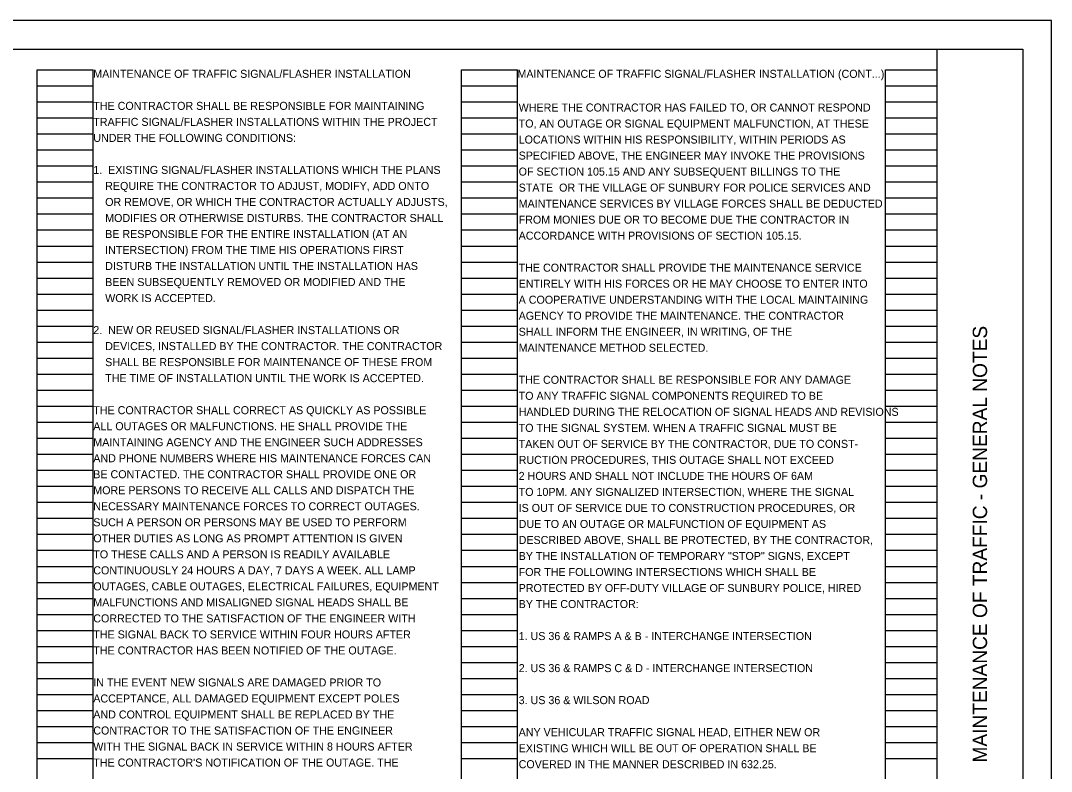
# Model space of a CAD drawing. Extents: x -6.8 to 34, y 0 to 22.
# Drawn here: x 15.97 to 34, y 8.88 to 22 of the extents above; entities that cross this region are included whole.
import ezdxf

# ---------------------------------------------------------------- set-up
doc = ezdxf.new("R2010")
doc.units = 0
for name, color, linetype in [('SH_Border', 7, 'Continuous'), ('SH_Cut_Line', 7, 'Continuous'), ('SH_Data', 7, 'Continuous'), ('SH_Text', 7, 'Continuous')]:
    doc.layers.add(name, color=color, linetype=linetype)

msp = doc.modelspace()

# ---------------------------------------------------------------- linework, layer by layer
at = {"layer": 'SH_Border'}
msp.add_line((32, 0.5), (32, 21.5), dxfattribs=at)
msp.add_lwpolyline([(1.5, 21.5), (33.5, 21.5), (33.5, 0.5), (1.5, 0.5)], close=True, dxfattribs=at)
at = {"layer": 'SH_Cut_Line'}
msp.add_lwpolyline([(0, 0), (34, 0), (34, 22), (0, 22)], close=True, dxfattribs=at)
at = {"layer": 'SH_Data'}
for p, q in [((16.26, 0.98), (16.26, 21.14)), ((16.26, 21.14), (17.24, 21.14)), ((17.24, 0.98), (17.24, 21.14)), ((23.68, 0.98), (23.68, 21.14)), ((23.68, 21.14), (24.66, 21.14)), ((24.66, 0.98), (24.66, 21.14)), ((31.1, 0.98), (31.1, 21.14)), ((31.1, 21.14), (32, 21.14)), ((32, 0.98), (32, 21.14)), ((16.26, 20.86), (17.24, 20.86)), ((23.68, 20.86), (24.66, 20.86)), ((31.1, 20.86), (32, 20.86)), ((16.26, 20.58), (17.24, 20.58)), ((23.68, 20.58), (24.66, 20.58)), ((31.1, 20.58), (32, 20.58)), ((16.26, 20.3), (17.24, 20.3)), ((23.68, 20.3), (24.66, 20.3)), ((31.1, 20.3), (32, 20.3)), ((16.26, 20.02), (17.24, 20.02)), ((23.68, 20.02), (24.66, 20.02)), ((31.1, 20.02), (32, 20.02)), ((16.26, 19.74), (17.24, 19.74)), ((23.68, 19.74), (24.66, 19.74)), ((31.1, 19.74), (32, 19.74)), ((16.26, 19.46), (17.24, 19.46)), ((23.68, 19.46), (24.66, 19.46)), ((31.1, 19.46), (32, 19.46)), ((16.26, 19.18), (17.24, 19.18)), ((23.68, 19.18), (24.66, 19.18)), ((31.1, 19.18), (32, 19.18)), ((16.26, 18.9), (17.24, 18.9)), ((23.68, 18.9), (24.66, 18.9)), ((31.1, 18.9), (32, 18.9)), ((16.26, 18.62), (17.24, 18.62)), ((23.68, 18.62), (24.66, 18.62)), ((31.1, 18.62), (32, 18.62)), ((16.26, 18.34), (17.24, 18.34)), ((23.68, 18.34), (24.66, 18.34)), ((31.1, 18.34), (32, 18.34)), ((16.26, 18.06), (17.24, 18.06)), ((23.68, 18.06), (24.66, 18.06)), ((31.1, 18.06), (32, 18.06)), ((16.26, 17.78), (17.24, 17.78)), ((23.68, 17.78), (24.66, 17.78)), ((31.1, 17.78), (32, 17.78)), ((16.26, 17.5), (17.24, 17.5)), ((23.68, 17.5), (24.66, 17.5)), ((31.1, 17.5), (32, 17.5)), ((16.26, 17.22), (17.24, 17.22)), ((23.68, 17.22), (24.66, 17.22)), ((31.1, 17.22), (32, 17.22)), ((16.26, 16.94), (17.24, 16.94)), ((23.68, 16.94), (24.66, 16.94)), ((31.1, 16.94), (32, 16.94)), ((16.26, 16.66), (17.24, 16.66)), ((23.68, 16.66), (24.66, 16.66)), ((31.1, 16.66), (32, 16.66)), ((16.26, 16.38), (17.24, 16.38)), ((23.68, 16.38), (24.66, 16.38)), ((31.1, 16.38), (32, 16.38)), ((16.26, 16.1), (17.24, 16.1)), ((23.68, 16.1), (24.66, 16.1)), ((31.1, 16.1), (32, 16.1)), ((16.26, 15.82), (17.24, 15.82)), ((23.68, 15.82), (24.66, 15.82)), ((31.1, 15.82), (32, 15.82)), ((16.26, 15.54), (17.24, 15.54)), ((23.68, 15.54), (24.66, 15.54)), ((31.1, 15.54), (32, 15.54)), ((16.26, 15.26), (17.24, 15.26)), ((23.68, 15.26), (24.66, 15.26)), ((31.1, 15.26), (32, 15.26)), ((16.26, 14.98), (17.24, 14.98)), ((23.68, 14.98), (24.66, 14.98)), ((31.1, 14.98), (32, 14.98)), ((16.26, 14.7), (17.24, 14.7)), ((23.68, 14.7), (24.66, 14.7)), ((31.1, 14.7), (32, 14.7)), ((16.26, 14.42), (17.24, 14.42)), ((23.68, 14.42), (24.66, 14.42)), ((31.1, 14.42), (32, 14.42)), ((16.26, 14.14), (17.24, 14.14)), ((23.68, 14.14), (24.66, 14.14)), ((31.1, 14.14), (32, 14.14)), ((16.26, 13.86), (17.24, 13.86)), ((23.68, 13.86), (24.66, 13.86)), ((31.1, 13.86), (32, 13.86)), ((16.26, 13.58), (17.24, 13.58)), ((23.68, 13.58), (24.66, 13.58)), ((31.1, 13.58), (32, 13.58)), ((16.26, 13.3), (17.24, 13.3)), ((23.68, 13.3), (24.66, 13.3)), ((31.1, 13.3), (32, 13.3)), ((16.26, 13.02), (17.24, 13.02)), ((23.68, 13.02), (24.66, 13.02)), ((31.1, 13.02), (32, 13.02)), ((16.26, 12.74), (17.24, 12.74)), ((23.68, 12.74), (24.66, 12.74)), ((31.1, 12.74), (32, 12.74)), ((16.26, 12.46), (17.24, 12.46)), ((23.68, 12.46), (24.66, 12.46)), ((31.1, 12.46), (32, 12.46)), ((16.26, 12.18), (17.24, 12.18)), ((23.68, 12.18), (24.66, 12.18)), ((31.1, 12.18), (32, 12.18)), ((16.26, 11.9), (17.24, 11.9)), ((23.68, 11.9), (24.66, 11.9)), ((31.1, 11.9), (32, 11.9)), ((16.26, 11.62), (17.24, 11.62)), ((23.68, 11.62), (24.66, 11.62)), ((31.1, 11.62), (32, 11.62)), ((16.26, 11.34), (17.24, 11.34)), ((23.68, 11.34), (24.66, 11.34)), ((31.1, 11.34), (32, 11.34)), ((16.26, 11.06), (17.24, 11.06)), ((23.68, 11.06), (24.66, 11.06)), ((31.1, 11.06), (32, 11.06)), ((16.26, 10.78), (17.24, 10.78)), ((23.68, 10.78), (24.66, 10.78)), ((31.1, 10.78), (32, 10.78)), ((16.26, 10.5), (17.24, 10.5)), ((23.68, 10.5), (24.66, 10.5)), ((31.1, 10.5), (32, 10.5)), ((16.26, 10.22), (17.24, 10.22)), ((23.68, 10.22), (24.66, 10.22)), ((31.1, 10.22), (32, 10.22)), ((16.26, 9.94), (17.24, 9.94)), ((23.68, 9.94), (24.66, 9.94)), ((31.1, 9.94), (32, 9.94)), ((16.26, 9.66), (17.24, 9.66)), ((23.68, 9.66), (24.66, 9.66)), ((31.1, 9.66), (32, 9.66)), ((16.26, 9.38), (17.24, 9.38)), ((23.68, 9.38), (24.66, 9.38)), ((31.1, 9.38), (32, 9.38)), ((16.26, 9.1), (17.24, 9.1)), ((23.68, 9.1), (24.66, 9.1)), ((31.1, 9.1), (32, 9.1))]:
    msp.add_line(p, q, dxfattribs=at)

# ---------------------------------------------------------------- texts
msp.add_text('MAINTENANCE OF TRAFFIC - GENERAL NOTES', height=0.25, rotation=90, dxfattribs=at).set_placement((32.875, 9.03))
at = {"layer": 'SH_Text'}
for s, p in [('MAINTENANCE OF TRAFFIC SIGNAL/FLASHER INSTALLATION', (17.24, 21)), ('MAINTENANCE OF TRAFFIC SIGNAL/FLASHER INSTALLATION (CONT...)', (24.66, 21)), ('THE CONTRACTOR SHALL BE RESPONSIBLE FOR MAINTAINING', (17.24, 20.44)), ('WHERE THE CONTRACTOR HAS FAILED TO, OR CANNOT RESPOND', (24.681, 20.411)), ('TRAFFIC SIGNAL/FLASHER INSTALLATIONS WITHIN THE PROJECT', (17.24, 20.16)), ('TO, AN OUTAGE OR SIGNAL EQUIPMENT MALFUNCTION, AT THESE', (24.681, 20.131)), ('UNDER THE FOLLOWING CONDITIONS:', (17.24, 19.88)), ('LOCATIONS WITHIN HIS RESPONSIBILITY, WITHIN PERIODS AS', (24.681, 19.851)), ('SPECIFIED ABOVE, THE ENGINEER MAY INVOKE THE PROVISIONS', (24.681, 19.571)), ('1.  EXISTING SIGNAL/FLASHER INSTALLATIONS WHICH THE PLANS', (17.24, 19.32)), ('OF SECTION 105.15 AND ANY SUBSEQUENT BILLINGS TO THE', (24.681, 19.291)), ('    REQUIRE THE CONTRACTOR TO ADJUST, MODIFY, ADD ONTO', (17.24, 19.04)), ('STATE  OR THE VILLAGE OF SUNBURY FOR POLICE SERVICES AND', (24.681, 19.011)), ('    OR REMOVE, OR WHICH THE CONTRACTOR ACTUALLY ADJUSTS,', (17.24, 18.76)), ('MAINTENANCE SERVICES BY VILLAGE FORCES SHALL BE DEDUCTED', (24.681, 18.731)), ('    MODIFIES OR OTHERWISE DISTURBS. THE CONTRACTOR SHALL', (17.24, 18.48)), ('FROM MONIES DUE OR TO BECOME DUE THE CONTRACTOR IN', (24.681, 18.451)), ('    BE RESPONSIBLE FOR THE ENTIRE INSTALLATION (AT AN', (17.24, 18.2)), ('ACCORDANCE WITH PROVISIONS OF SECTION 105.15.', (24.681, 18.171)), ('    INTERSECTION) FROM THE TIME HIS OPERATIONS FIRST', (17.24, 17.92)), ('    DISTURB THE INSTALLATION UNTIL THE INSTALLATION HAS', (17.24, 17.64)), ('THE CONTRACTOR SHALL PROVIDE THE MAINTENANCE SERVICE', (24.681, 17.611)), ('    BEEN SUBSEQUENTLY REMOVED OR MODIFIED AND THE', (17.24, 17.36)), ('ENTIRELY WITH HIS FORCES OR HE MAY CHOOSE TO ENTER INTO', (24.681, 17.331)), ('    WORK IS ACCEPTED.', (17.24, 17.08)), ('A COOPERATIVE UNDERSTANDING WITH THE LOCAL MAINTAINING', (24.681, 17.051)), ('AGENCY TO PROVIDE THE MAINTENANCE. THE CONTRACTOR', (24.681, 16.771)), ('2.  NEW OR REUSED SIGNAL/FLASHER INSTALLATIONS OR', (17.24, 16.52)), ('SHALL INFORM THE ENGINEER, IN WRITING, OF THE', (24.681, 16.491)), ('    DEVICES, INSTALLED BY THE CONTRACTOR. THE CONTRACTOR', (17.24, 16.24)), ('MAINTENANCE METHOD SELECTED.', (24.681, 16.211)), ('    SHALL BE RESPONSIBLE FOR MAINTENANCE OF THESE FROM', (17.24, 15.96)), ('    THE TIME OF INSTALLATION UNTIL THE WORK IS ACCEPTED.', (17.24, 15.68)), ('THE CONTRACTOR SHALL BE RESPONSIBLE FOR ANY DAMAGE', (24.681, 15.651)), ('TO ANY TRAFFIC SIGNAL COMPONENTS REQUIRED TO BE', (24.681, 15.371)), ('THE CONTRACTOR SHALL CORRECT AS QUICKLY AS POSSIBLE', (17.24, 15.12)), ('HANDLED DURING THE RELOCATION OF SIGNAL HEADS AND REVISIONS', (24.681, 15.091)), ('ALL OUTAGES OR MALFUNCTIONS. HE SHALL PROVIDE THE', (17.24, 14.84)), ('TO THE SIGNAL SYSTEM. WHEN A TRAFFIC SIGNAL MUST BE', (24.681, 14.811)), ('MAINTAINING AGENCY AND THE ENGINEER SUCH ADDRESSES', (17.24, 14.56)), ('TAKEN OUT OF SERVICE BY THE CONTRACTOR, DUE TO CONST-', (24.681, 14.531)), ('AND PHONE NUMBERS WHERE HIS MAINTENANCE FORCES CAN', (17.24, 14.28)), ('RUCTION PROCEDURES, THIS OUTAGE SHALL NOT EXCEED', (24.681, 14.251)), ('BE CONTACTED. THE CONTRACTOR SHALL PROVIDE ONE OR', (17.24, 14)), ('2 HOURS AND SHALL NOT INCLUDE THE HOURS OF 6AM', (24.681, 13.971)), ('MORE PERSONS TO RECEIVE ALL CALLS AND DISPATCH THE', (17.24, 13.72)), ('TO 10PM. ANY SIGNALIZED INTERSECTION, WHERE THE SIGNAL', (24.681, 13.691)), ('NECESSARY MAINTENANCE FORCES TO CORRECT OUTAGES.', (17.24, 13.44)), ('IS OUT OF SERVICE DUE TO CONSTRUCTION PROCEDURES, OR', (24.681, 13.411)), ('SUCH A PERSON OR PERSONS MAY BE USED TO PERFORM', (17.24, 13.16)), ('DUE TO AN OUTAGE OR MALFUNCTION OF EQUIPMENT AS', (24.681, 13.131)), ('OTHER DUTIES AS LONG AS PROMPT ATTENTION IS GIVEN', (17.24, 12.88)), ('DESCRIBED ABOVE, SHALL BE PROTECTED, BY THE CONTRACTOR,', (24.681, 12.851)), ('TO THESE CALLS AND A PERSON IS READILY AVAILABLE', (17.24, 12.6)), ('BY THE INSTALLATION OF TEMPORARY "STOP" SIGNS, EXCEPT', (24.681, 12.571)), ('CONTINUOUSLY 24 HOURS A DAY, 7 DAYS A WEEK. ALL LAMP', (17.24, 12.32)), ('FOR THE FOLLOWING INTERSECTIONS WHICH SHALL BE', (24.681, 12.291)), ('OUTAGES, CABLE OUTAGES, ELECTRICAL FAILURES, EQUIPMENT', (17.24, 12.04)), ('PROTECTED BY OFF-DUTY VILLAGE OF SUNBURY POLICE, HIRED', (24.681, 12.011)), ('MALFUNCTIONS AND MISALIGNED SIGNAL HEADS SHALL BE', (17.24, 11.76)), ('BY THE CONTRACTOR:', (24.681, 11.731)), ('CORRECTED TO THE SATISFACTION OF THE ENGINEER WITH', (17.24, 11.48)), ('THE SIGNAL BACK TO SERVICE WITHIN FOUR HOURS AFTER', (17.24, 11.2)), ('1. US 36 & RAMPS A & B - INTERCHANGE INTERSECTION', (24.681, 11.171)), ('THE CONTRACTOR HAS BEEN NOTIFIED OF THE OUTAGE.', (17.24, 10.92)), ('2. US 36 & RAMPS C & D - INTERCHANGE INTERSECTION', (24.681, 10.611)), ('IN THE EVENT NEW SIGNALS ARE DAMAGED PRIOR TO', (17.24, 10.36)), ('ACCEPTANCE, ALL DAMAGED EQUIPMENT EXCEPT POLES', (17.24, 10.08)), ('3. US 36 & WILSON ROAD', (24.681, 10.051)), ('AND CONTROL EQUIPMENT SHALL BE REPLACED BY THE', (17.24, 9.8)), ('CONTRACTOR TO THE SATISFACTION OF THE ENGINEER', (17.24, 9.52)), ('ANY VEHICULAR TRAFFIC SIGNAL HEAD, EITHER NEW OR', (24.681, 9.491)), ('WITH THE SIGNAL BACK IN SERVICE WITHIN 8 HOURS AFTER', (17.24, 9.24)), ('EXISTING WHICH WILL BE OUT OF OPERATION SHALL BE', (24.681, 9.211)), ("THE CONTRACTOR'S NOTIFICATION OF THE OUTAGE. THE", (17.24, 8.96)), ('COVERED IN THE MANNER DESCRIBED IN 632.25.', (24.681, 8.931))]:
    msp.add_text(s, height=0.14, dxfattribs=at).set_placement(p)

doc.saveas('drawing.dxf')
